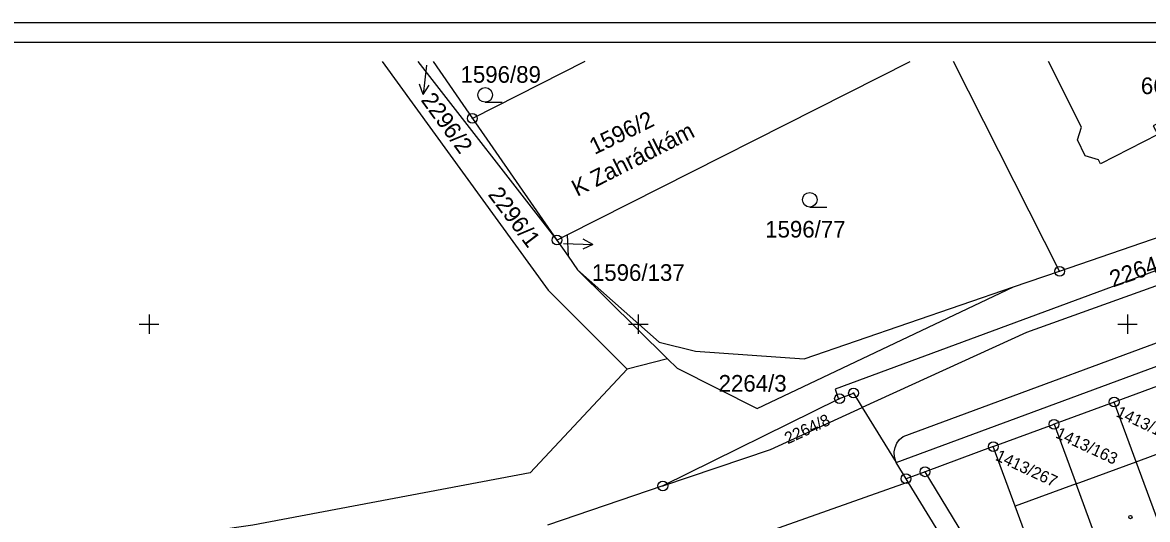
# Model space of a CAD drawing. Extents: x -771260 to -770828, y -1053564 to -1052811.
# Drawn here: x -771112.9 to -770998, y -1053020 to -1052969.2 of the extents above; entities that cross this region are included whole.
import ezdxf

# ---------------------------------------------------------------- set-up
doc = ezdxf.new("R2010")
doc.units = 0
for name, color, linetype in [('14_8_2023_krizky', 7, 'Continuous'), ('25_3_2019_krizky_JTSK', 7, 'Continuous'), ('25_3_2019_ram_ggs', 7, 'Continuous'), ('DKM_Hranice parcel', 7, 'Continuous'), ('DKM_Parcelní čísla', 7, 'Continuous'), ('DKM_Pop  PČ popisy', 7, 'Continuous'), ('DKM_Značky bodu BP', 7, 'Continuous'), ('DKM_Značky budov', 7, 'Continuous'), ('DKM_Značky kultur', 7, 'Continuous')]:
    doc.layers.add(name, color=color, linetype=linetype)

# ---------------------------------------------------------------- blocks, each defined once
blk = doc.blocks.new('KRIZEK')
at = {"layer": '25_3_2019_krizky_JTSK'}
for p, q in [((-10, 0), (10, 0)), ((0, 10), (0, -10))]:
    blk.add_line(p, q, dxfattribs=at)

msp = doc.modelspace()

# ---------------------------------------------------------------- linework, layer by layer
at = {"layer": '25_3_2019_ram_ggs'}
for points in [[(-771251.02, -1053563.67), (-771251.02, -1052969.17), (-770830.52, -1052969.17), (-770830.52, -1053563.67)], [(-771249.02, -1053561.67), (-771249.02, -1052971.17), (-770832.52, -1052971.17), (-770832.52, -1053561.67)]]:
    msp.add_lwpolyline(points, close=True, dxfattribs=at)
at = {"layer": 'DKM_Hranice parcel'}
for p, q in [((-771055.48, -1052973.17), (-771066.96, -1052978.97)), ((-771057.28, -1052990.89), (-771022.2, -1052973.17)), ((-771006.94, -1052994.6), (-771017.77, -1052973.17)), ((-771066.96, -1052978.97), (-771058.31, -1052991.41)), ((-771006.94, -1052994.6), (-770975.72, -1052983.82)), ((-771058.31, -1052991.41), (-771057.28, -1052990.89)), ((-771057.28, -1052990.89), (-771057.17, -1052993.06)), ((-771058.31, -1052991.41), (-771057.17, -1052993.06)), ((-771057.17, -1052993.06), (-771056.2, -1052994.46)), ((-771056.2, -1052994.46), (-771047.02, -1053003.53)), ((-771011.65, -1052996.2), (-771006.94, -1052994.6)), ((-771047.02, -1053003.53), (-771051.12, -1053004.61)), ((-770995.21, -1053005.7), (-771001.36, -1053007.96)), ((-771029.52, -1053007.66), (-771047.49, -1053016.54)), ((-771001.36, -1053007.96), (-771007.5, -1053010.23)), ((-770999.11, -1053014.06), (-771001.36, -1053007.96)), ((-771027.1, -1053008.51), (-771023.65, -1053014.13)), ((-771013.72, -1053012.52), (-771007.5, -1053010.23)), ((-771007.5, -1053010.23), (-771005.26, -1053016.33)), ((-770999.11, -1053014.06), (-770992.96, -1053011.8)), ((-771013.72, -1053012.52), (-771020.69, -1053015.09)), ((-771011.47, -1053018.62), (-771013.72, -1053012.52)), ((-771022.63, -1053015.8), (-771023.65, -1053014.13)), ((-771005.26, -1053016.33), (-770999.11, -1053014.06)), ((-770994.58, -1053026.36), (-770999.11, -1053014.06)), ((-771020.69, -1053015.09), (-771022.63, -1053015.8)), ((-770983.17, -1053076.38), (-771020.69, -1053015.09)), ((-771022.41, -1053016.16), (-771022.63, -1053015.8)), ((-771005.26, -1053016.33), (-771011.47, -1053018.62)), ((-771000.73, -1053028.62), (-771005.26, -1053016.33)), ((-771047.49, -1053016.54), (-771059.27, -1053020.54))]:
    msp.add_line(p, q, dxfattribs=at)
for points in [[(-771076.17, -1052973.17), (-771059.2, -1052996.52), (-771051.12, -1053004.61)], [(-771072.54, -1052973.17), (-771058.31, -1052991.41)], [(-771070.98, -1052973.17), (-771066.96, -1052978.97)], [(-770941.9, -1052973.17), (-770957.22, -1052979.8), (-771029.87, -1053006.66), (-771029.52, -1053007.66)], [(-770936.29, -1052973.17), (-770940.68, -1052975.28), (-770955.34, -1052981.32), (-770982.73, -1052990.94), (-771010.32, -1053000.85), (-771027.1, -1053008.51)], [(-771023.65, -1053014.13), (-770952.75, -1052987.96), (-770918.46, -1052973.17)], [(-771022.94, -1053011.48), (-770953.62, -1052985.88), (-770924.11, -1052973.17)], [(-771004.69, -1052979.87), (-771008.06, -1052973.17)], [(-770984.48, -1052973.17), (-770983.11, -1052975.87), (-770989, -1052978.86), (-770990.36, -1052976.18), (-770997.36, -1052979.74), (-770996.91, -1052980.63), (-771002.76, -1052983.62), (-771002.97, -1052983.2), (-771004.33, -1052982.79), (-771005.11, -1052981.18), (-771004.69, -1052979.87)], [(-771056.2, -1052994.46), (-771047.87, -1053001.83), (-771044.16, -1053002.77)], [(-771047.02, -1053003.53), (-771046.04, -1053004.49), (-771037.86, -1053008.61), (-771011.65, -1052996.2)], [(-771044.16, -1053002.77), (-771033.06, -1053003.55), (-771011.65, -1052996.2)], [(-771051.12, -1053004.61), (-771061.04, -1053015.19), (-771089.41, -1053020.54), (-771104.76, -1053022.75)], [(-771029.52, -1053007.66), (-771029.43, -1053007.61), (-771028, -1053007.04), (-771027.1, -1053008.51)], [(-771047.49, -1053016.54), (-771036.5, -1053012.8), (-771027.1, -1053008.51)], [(-771023.65, -1053014.13), (-771023.79, -1053013.69), (-771023.84, -1053013.22), (-771023.83, -1053013.06), (-771023.74, -1053012.6), (-771023.56, -1053012.17), (-771023.29, -1053011.79), (-771022.94, -1053011.48)], [(-771022.41, -1053016.16), (-771043.39, -1053023.58), (-771052.21, -1053026.69)], [(-770991.72, -1053066.27), (-771003.86, -1053046.45), (-771022.41, -1053016.16)], [(-771000.73, -1053028.62), (-771006.94, -1053030.91), (-771011.47, -1053018.62)]]:
    msp.add_lwpolyline(points, dxfattribs=at)
at = {"layer": 'DKM_Pop  PČ popisy'}
for p, q in [((-771071.65, -1052973.54), (-771071.97, -1052976.52)), ((-771071.97, -1052976.52), (-771072.36, -1052975.48)), ((-771071.97, -1052976.52), (-771071.36, -1052975.58)), ((-771057.64, -1052991.76), (-771054.64, -1052991.86)), ((-771054.64, -1052991.86), (-771055.66, -1052992.33)), ((-771054.64, -1052991.86), (-771055.62, -1052991.33))]:
    msp.add_line(p, q, dxfattribs=at)
at = {"layer": 'DKM_Značky bodu BP'}
for centre, radius in [((-771066.96, -1052978.97), 0.5), ((-771066.96, -1052978.97), 0.0303), ((-771058.31, -1052991.41), 0.5), ((-771058.31, -1052991.41), 0.0303), ((-771006.94, -1052994.6), 0.5), ((-771006.94, -1052994.6), 0.0303), ((-771029.43, -1053007.61), 0.5), ((-771028, -1053007.04), 0.5), ((-771028, -1053007.04), 0.0303), ((-771029.43, -1053007.61), 0.0303), ((-771001.36, -1053007.96), 0.5), ((-771001.36, -1053007.96), 0.0303), ((-771007.5, -1053010.23), 0.5), ((-771007.5, -1053010.23), 0.0303), ((-771013.72, -1053012.52), 0.5), ((-771013.72, -1053012.52), 0.0303), ((-771022.63, -1053015.8), 0.5), ((-771020.69, -1053015.09), 0.5), ((-771020.69, -1053015.09), 0.0303), ((-771047.49, -1053016.54), 0.5), ((-771047.49, -1053016.54), 0.0303), ((-771022.63, -1053015.8), 0.0303)]:
    msp.add_circle(centre, radius, dxfattribs=at)
at = {"layer": 'DKM_Značky budov'}
msp.add_circle((-770999.7, -1053019.72), 0.175, dxfattribs=at)
at = {"layer": 'DKM_Značky kultur'}
for p, q in [((-771065.65, -1052977.32), (-771063.9, -1052977.32)), ((-771032.47, -1052988.04), (-771030.72, -1052988.04))]:
    msp.add_line(p, q, dxfattribs=at)
for centre in [(-771065.65, -1052976.57), (-771032.47, -1052987.29)]:
    msp.add_circle(centre, 0.75, dxfattribs=at)

# ---------------------------------------------------------------- block references
at = {"layer": '14_8_2023_krizky', "xscale": 0.1, "yscale": 0.10000000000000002}
for p in [(-771100, -1053000), (-771050, -1053000), (-771000, -1053000)]:
    msp.add_blockref('KRIZEK', p, dxfattribs=at)

# ---------------------------------------------------------------- texts
at = {"layer": 'DKM_Parcelní čísla'}
for s, p in [('1596/89', (-771068.17, -1052975.33)), ('6642', (-770998.63, -1052976.49)), ('1596/77', (-771037.03, -1052991.15)), ('1596/137', (-771054.74, -1052995.58)), ('2264/3', (-771041.79, -1053006.9))]:
    msp.add_text(s, height=1.7, dxfattribs=at).set_placement(p)
for s, height, rotation, p in [('2296/2', 1.7, 306, (-771072.28, -1052977.11)), ('1596/2', 1.7, 26, (-771054.47, -1052982.72)), ('2296/1', 1.7, 307, (-771065.43, -1052986.77)), ('2264/11', 1.7, 19, (-771001.47, -1052996.25)), ('2264/8', 1.2, 25, (-771034.71, -1053012.29)), ('1413/164', 1.2, 335, (-771001.25, -1053009.4)), ('1413/163', 1.2, 335, (-771007.43, -1053011.56)), ('1413/267', 1.2, 335, (-771013.59, -1053013.86))]:
    msp.add_text(s, height=height, rotation=rotation, dxfattribs=at).set_placement(p)
at = {"layer": 'DKM_Pop  PČ popisy'}
msp.add_text('K Zahrádkám', height=1.7, rotation=27, dxfattribs=at).set_placement((-771056.25, -1052987))

doc.saveas('drawing.dxf')
